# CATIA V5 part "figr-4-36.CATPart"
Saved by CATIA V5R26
Part number: Part1
Bounding box of the stored display mesh (mm): x 0 to 79, y -70 to 90, z -90 to 70
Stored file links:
  D:\_Deepak\CATIA\CATIA V5-6R2016_Deepak\Resources\Part files\Partfiles\c04_catia_v5_6r2016_prt\figr-4-36.CATPart
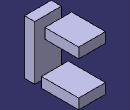
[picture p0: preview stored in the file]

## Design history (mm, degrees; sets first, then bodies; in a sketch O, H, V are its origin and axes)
Body1 (main body)
  Sketch1 on yz-plane, origin (0, 0, 0), H (0, 1, 0), V (0, 0, 1)
    line L1 (-100, 100) -> (100, 100)
    line L2 (100, 100) -> (100, -100)
    line L3 (100, -100) -> (-100, -100)
    line L4 (-100, -100) -> (-100, 100)
    line L5 (-70, 70) -> (-40, 70)
    line L6 (-40, 70) -> (-40, -90)
    line L7 (-40, -90) -> (-70, -90)
    line L8 (-70, -90) -> (-70, 70)
    line L9 (-10, 70) -> (90, 70)
    line L10 (90, 70) -> (90, 40)
    line L11 (90, 40) -> (-10, 40)
    line L12 (-10, 40) -> (-10, 70)
    point P13 (90, -90)
    line L13 (90, -90) -> (-20, -90)
    line L14 (-20, -90) -> (-20, -60)
    line L15 (-20, -60) -> (90, -60)
    line L16 (90, -60) -> (90, -90)
    horizontal: L1 H, L3 H, L5 H, L7 H, L9 H, L11 H, L13 H, L15 H
    vertical: L2 V, L4 V, L6 V, L8 V, L10 V, L12 V, L14 V, L16 V
    coincidence: P13 L10, P13 L7
  Pad1: profile edge of Sketch1, length 79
